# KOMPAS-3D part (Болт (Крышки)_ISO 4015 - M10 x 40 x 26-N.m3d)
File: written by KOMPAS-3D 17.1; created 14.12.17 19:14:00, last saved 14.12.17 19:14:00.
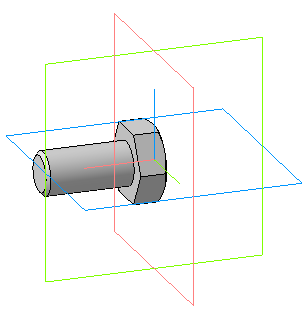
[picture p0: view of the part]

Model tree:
1. Операция без истории:1  (labels: Болт (Крышки)_ISO 4015 - M10 x 40 x 26-N)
